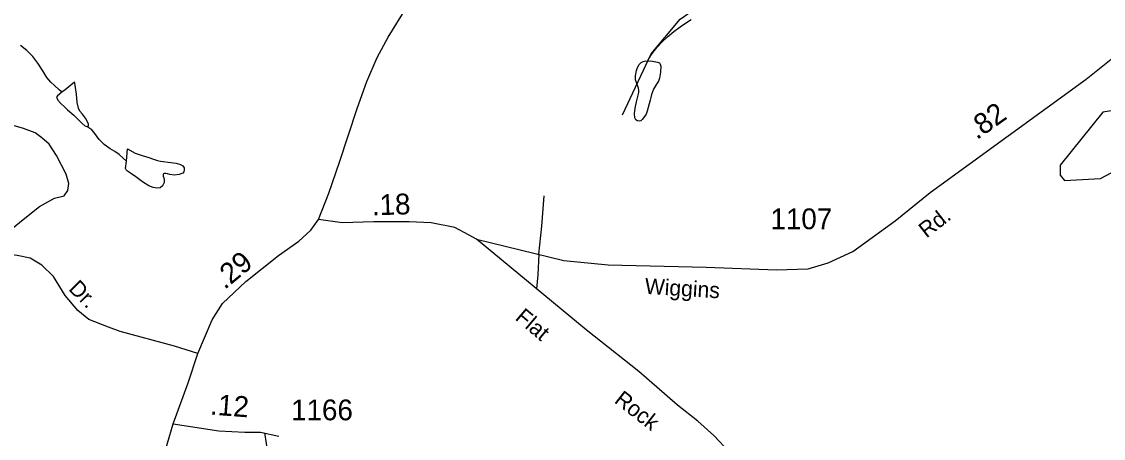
# Model space of a CAD drawing. Extents: x 2126262 to 2293712, y 749403 to 919119.
# Drawn here: x 2169962 to 2176471, y 829162 to 831672 of the extents above; entities that cross this region are included whole.
import ezdxf

# ---------------------------------------------------------------- set-up
doc = ezdxf.new("R2010")
doc.units = 0
for name, color, linetype in [('Exist Hydrographic Misc Water Feature', 7, 'Continuous'), ('Exist Hydrographic Pond Under 1500 Sq Ft', 7, 'Continuous'), ('Exist Road Non-System Type 51', 7, 'Continuous'), ('Exist Road Non-System Type 51 Label', 7, 'Continuous'), ('Exist Road Secondary Mileage Hundredths English Label', 7, 'Continuous'), ('Exist Road Secondary Type 51 Attributed', 7, 'Continuous'), ('Exist Road Secondary Type 51 Label', 7, 'Continuous'), ('Exist Road Secondary Type 51 Number Label', 7, 'Continuous')]:
    doc.layers.add(name, color=color, linetype=linetype)

msp = doc.modelspace()

# ---------------------------------------------------------------- linework, layer by layer
at = {"layer": 'Exist Hydrographic Misc Water Feature'}
for points in [[(2173577.4, 831111), (2173750.5, 831478.1), (2173924.5, 831687.8), (2174521.5, 832105.2), (2174786.4, 832349), (2174869.4, 832491.7), (2175039.4, 833350.9), (2175228.5, 833760.4), (2175452.4, 833969), (2175651.5, 834079.7), (2175867.4, 834154), (2175934.5, 834247.7), (2175956.4, 834621.2), (2176005.4, 834781), (2176113.5, 834913.3)], [(2173728, 831434.9), (2173737.9, 831453), (2173751.8, 831475.1), (2173769.6, 831499.2), (2173785.6, 831519.3), (2173815.4, 831551.5), (2173849, 831581.5), (2173887.1, 831611.8), (2173924.9, 831640), (2173962.6, 831666.2), (2173990.5, 831684.4)], [(2170204, 831247.1), (2170200.1, 831251.1), (2170188, 831261), (2170159.9, 831286.8), (2170137.8, 831306.7), (2170113.6, 831336.6), (2170089.4, 831376.4), (2170059, 831422.2), (2170028.9, 831462.1), (2169992.8, 831497.8), (2169956.5, 831527.6)], [(2173728, 831434.9), (2173748.1, 831435.1), (2173788.1, 831427.3), (2173800, 831423.4), (2173804.1, 831415.4), (2173808, 831403.5), (2173806.3, 831367.4), (2173800.6, 831331.4), (2173794.7, 831313.4), (2173782.8, 831295.3), (2173765.1, 831265.2), (2173753, 831233.1), (2173747.3, 831215.1), (2173743.4, 831199.1), (2173725.8, 831133), (2173719.8, 831115), (2173709.8, 831101), (2173696, 831082.9), (2173688, 831074.8), (2173680, 831072.8), (2173668.1, 831074.7), (2173658.1, 831080.6), (2173652.1, 831092.7), (2173649.9, 831116.6), (2173653.6, 831150.6), (2173661.4, 831188.6), (2173669.4, 831220.7), (2173675.1, 831244.7), (2173675.1, 831256.7), (2173673.1, 831270.7), (2173664.9, 831292.6), (2173656.7, 831322.6), (2173656.7, 831346.6), (2173662.4, 831378.5), (2173668.3, 831396.6), (2173678, 831414.7), (2173690.1, 831426.7), (2173702, 831432.8), (2173718, 831436.9), (2173728, 831434.9)], [(2170355.3, 831040), (2170361.3, 831040.1), (2170365.4, 831042.1), (2170365.2, 831056.1), (2170346.9, 831089.9), (2170328.9, 831115.9), (2170312.9, 831133.7), (2170304.5, 831151.7), (2170296.3, 831185.6), (2170292.2, 831235.6), (2170285.8, 831275.6), (2170281.9, 831301.5), (2170279.9, 831307.5), (2170224.1, 831261.3), (2170204, 831247.1)], [(2170204, 831247.1), (2170178.4, 831225), (2170172.4, 831216.9), (2170180.4, 831199), (2170196.6, 831181), (2170222.7, 831157.2), (2170238.6, 831141.3), (2170276.8, 831109.6), (2170299.1, 831087.7), (2170325, 831059.8), (2170343.2, 831043.9), (2170355.3, 831040)], [(2170592.4, 830831.4), (2170574.3, 830847.3), (2170550.1, 830871.1), (2170524.1, 830891), (2170495.8, 830906.9), (2170459.9, 830932.6), (2170429.6, 830962.4), (2170397.4, 831006.2), (2170385.3, 831020.2), (2170355.3, 831040)], [(2170592.4, 830831.4), (2170599.7, 830905.4), (2170646.1, 830879.7), (2170688.1, 830865.9), (2170728.1, 830854.2), (2170756.4, 830844.3), (2170780.4, 830836.5), (2170798.2, 830832.5), (2170860.4, 830822.9), (2170892.4, 830819.1), (2170918.4, 830811.2), (2170932.3, 830803.4), (2170940.5, 830791.4), (2170940.5, 830779.4), (2170938.5, 830767.3), (2170932.5, 830759.3), (2170910.6, 830751.2), (2170880.9, 830747), (2170854.8, 830750.9), (2170840.5, 830754.9), (2170830.6, 830756.8), (2170820.6, 830756.7), (2170816.9, 830754.7), (2170814.8, 830750.7), (2170814.8, 830740.7), (2170818.7, 830730.7), (2170820.8, 830716.7), (2170819.1, 830702.7), (2170809.1, 830682.7), (2170795.2, 830670.6), (2170775.3, 830668.5), (2170753.1, 830672.3), (2170727.1, 830684.2), (2170689.1, 830708), (2170648.8, 830737.7), (2170616.8, 830759.5), (2170598.5, 830771.5), (2170590.5, 830779.4), (2170586.6, 830787.4), (2170592.4, 830831.4)]]:
    msp.add_lwpolyline(points, dxfattribs=at)
at = {"layer": 'Exist Hydrographic Pond Under 1500 Sq Ft'}
msp.add_lwpolyline([(2176701.4, 831026.7), (2176634.5, 831152.8), (2176468.4, 831126.7), (2176211.5, 830807.3), (2176211.5, 830748.2), (2176237.5, 830714.9), (2176453.5, 830726.8), (2176702.4, 830859.4), (2176701.4, 831026.7)], dxfattribs=at)
at = {"layer": 'Exist Road Non-System Type 51'}
for points in [[(2169835.3, 830275.4), (2169828.3, 830324.3), (2169850.6, 830369), (2169895.3, 830417.8), (2169981.6, 830488.6), (2170069.5, 830558.5), (2170160.2, 830608.7), (2170217.4, 830622.7), (2170241.1, 830654.8), (2170246.6, 830697.6), (2170231.2, 830753.4), (2170172.6, 830865.2), (2170128, 830933.6), (2170084.7, 830972.7), (2170044.3, 831003.4), (2169974.5, 831028.5), (2169840.6, 831066.2)], [(2173075.1, 830270.9), (2173093.2, 830441.3), (2173107.2, 830622.8)], [(2171021.6, 829673.6), (2170881.4, 829717.6), (2170554.9, 829807), (2170484.5, 829831.4), (2170367.3, 829878.9), (2170300.3, 829933.3), (2170223.8, 830022), (2170154.8, 830137.2), (2170084.3, 830206.3), (2170014.5, 830246.8), (2169935, 830263.5), (2169835.3, 830275.4)], [(2173075.1, 830270.9), (2173068.8, 830147.3), (2173059.7, 830062.9)], [(2171424.1, 829195.4), (2171442.9, 829067.4), (2171456.1, 829009.4), (2171482.6, 828985.7), (2171499.4, 828957.8), (2171502.2, 828892.2), (2171500.8, 828724.6), (2171507.8, 828617.8), (2171503.6, 828486.5), (2171518.9, 828434.9), (2171569.1, 828386), (2171692.6, 828300.1), (2171751.2, 828249.8), (2171809.8, 828178.6), (2171862.8, 828099), (2171889.3, 828039), (2171896.3, 827979), (2171881, 827935.7), (2171841.9, 827877.6), (2171802.8, 827835.7), (2171780.5, 827775.7), (2171759.6, 827749.1), (2171660.5, 827767.3)]]:
    msp.add_lwpolyline(points, dxfattribs=at)
at = {"layer": 'Exist Road Secondary Type 51 Attributed'}
for points in [[(2171749.1, 830480), (2171811, 830639), (2171875.2, 830826.1), (2171981, 831149.1), (2172039.5, 831311.1), (2172100.9, 831455.6), (2172167.8, 831578.4), (2172397, 831950.6), (2172539.3, 832162.9), (2172728.5, 832460.5), (2172798.3, 832580.6), (2172851.3, 832703.5), (2172887.6, 832832), (2172929.2, 833040.4), (2172987.8, 833347.6), (2173039.6, 833641.3), (2173058.8, 833812.3), (2173041.3, 834132.8), (2173012.7, 834591.4), (2172991.1, 834826.7), (2172954.8, 835115.8), (2172867.6, 835514.4)], [(2172699.1, 830362.4), (2173224.4, 830233.2), (2173490.8, 830206.7), (2174081.7, 830193.4), (2174504.4, 830176.7), (2174694.8, 830182.9), (2174814.8, 830219.2), (2174963.4, 830287), (2175218.7, 830472.7), (2175428.7, 830643.7), (2176367.6, 831325.1), (2176598.5, 831510.1)], [(2170875.1, 829250.5), (2170963.7, 829497), (2171021.6, 829673.6), (2171108.8, 829875.4), (2171170.2, 829974.5), (2171311.1, 830107.2), (2171507.1, 830264.2), (2171629.9, 830350.8), (2171703.1, 830417.1), (2171749.1, 830480)], [(2172699.1, 830362.4), (2172651.7, 830388.9), (2172568, 830432.2), (2172425.7, 830461.5), (2172293.8, 830466.4), (2172081.8, 830466.4), (2171890.6, 830460.8), (2171749.1, 830480)], [(2174915.2, 827182.1), (2174876.1, 827212.8), (2174818.2, 827266.6), (2174752.6, 827349), (2174709.4, 827438.3), (2174685.7, 827505.3), (2174667.5, 827631.5), (2174660.5, 827779.5), (2174642.4, 828073.3), (2174634.1, 828306.5), (2174603.5, 828480.1), (2174574.2, 828603), (2174511.4, 828725.9), (2174444.4, 828823.6), (2174220.5, 829079.9), (2174127, 829179), (2174030.8, 829265.6), (2173908, 829361.9), (2173676.4, 829565.8), (2173358.3, 829817.1), (2172699.1, 830362.4)], [(2170434.5, 827568.7), (2170459.4, 827735.5), (2170492.8, 827938), (2170542.4, 828153.7), (2170616.3, 828416.2), (2170772.6, 828900.7), (2170875.1, 829250.5)], [(2170875.1, 829250.5), (2171148.5, 829207.2), (2171304.8, 829198.9), (2171399, 829199.6), (2171509.2, 829175.8)]]:
    msp.add_lwpolyline(points, dxfattribs=at)

# ---------------------------------------------------------------- texts
at = {"layer": 'Exist Road Non-System Type 51 Label'}
msp.add_text('Dr.', height=95, rotation=314.97238, dxfattribs=at).set_placement((2170239.7, 830058))
at = {"layer": 'Exist Road Secondary Mileage Hundredths English Label'}
for s, rotation, p in [('.82', 35.26896, (2175709.2, 830957.6)), ('.18', 1.92229, (2172071.5, 830505.1)), ('.29', 39.80644, (2171184, 830055)), ('.12', 355.6981, (2171093.3, 829306.3))]:
    msp.add_text(s, height=125, rotation=rotation, dxfattribs=at).set_placement(p)
at = {"layer": 'Exist Road Secondary Type 51 Label'}
for s, rotation, p in [('Rd.', 37.93026, (2175406.6, 830365.2)), ('Wiggins', 356.54366, (2173709.7, 830033.1)), ('Flat', 319.75096, (2172926.4, 829881.4)), ('Rock', 322.01996, (2173522.8, 829382))]:
    msp.add_text(s, height=95, rotation=rotation, dxfattribs=at).set_placement(p)
at = {"layer": 'Exist Road Secondary Type 51 Number Label'}
for s, p in [('1107', (2174467.7, 830422.1)), ('1166', (2171583.5, 829271.4))]:
    msp.add_text(s, height=125, dxfattribs=at).set_placement(p)

doc.saveas('drawing.dxf')
